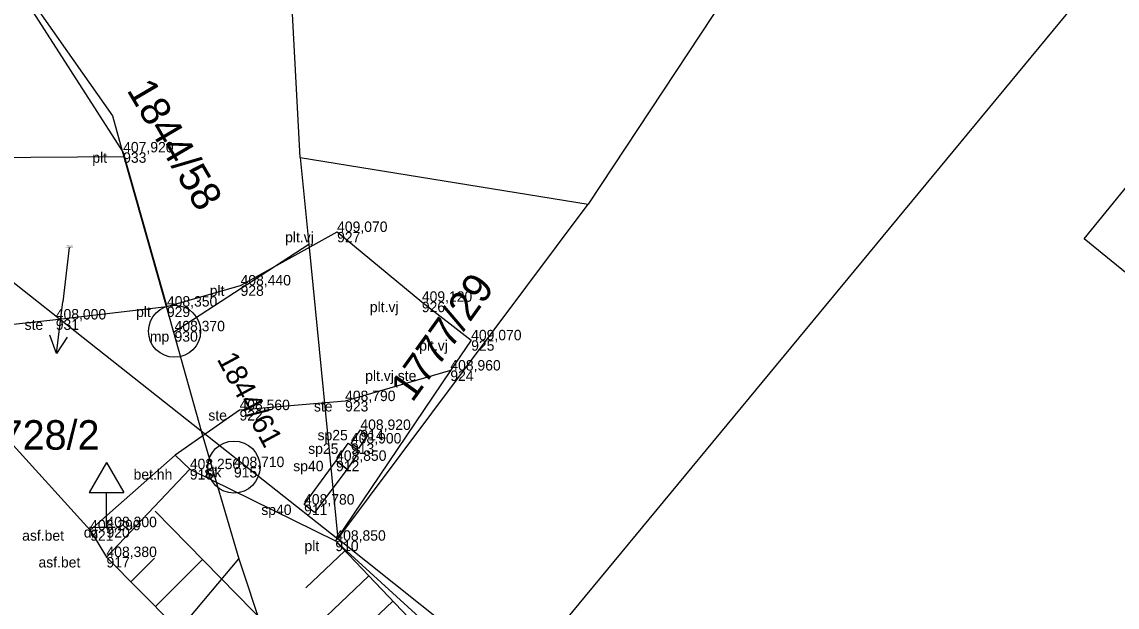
# Model space of a CAD drawing. Extents: x -747792 to -745414, y -1093712 to -1091463.
# Drawn here: x -746979.38 to -746947.84, y -1092227.92 to -1092211.07 of the extents above; entities that cross this region are included whole.
import ezdxf

# ---------------------------------------------------------------- set-up
doc = ezdxf.new("R2010")
doc.units = 0
for name, color, linetype in [('Doplňkové značky', 7, 'Continuous'), ('Hladina', 7, 'Continuous'), ('Koleje_dopravní prvky', 7, 'Continuous'), ('Nezařazené objekty', 7, 'Continuous'), ('Nivelační značky_hrany', 7, 'Continuous'), ('Názvy obcí_ulic', 7, 'Continuous'), ('Pracovní_bod PPBP', 7, 'Continuous'), ('Pracovní_bod PPBP - výška', 7, 'Continuous'), ('Rozhraní ploch', 7, 'Continuous'), ('Stromy_porost', 7, 'Continuous'), ('Výškopis', 7, 'Continuous'), ('Čísla popisná_parcelní', 7, 'Continuous')]:
    doc.layers.add(name, color=color, linetype=linetype)

msp = doc.modelspace()

# ---------------------------------------------------------------- linework, layer by layer
at = {"layer": 'Doplňkové značky'}
for points in [[(-746978.01, -1092217.57), (-746978.2, -1092219.13)], [(-746978.38, -1092220.619), (-746978.2, -1092219.13)], [(-746978.072, -1092220.153), (-746978.38, -1092220.619), (-746978.568, -1092220.093)]]:
    msp.add_lwpolyline(points, dxfattribs=at)
at = {"layer": 'Hladina'}
for p, q in [((-746976.46, -1092214.83), (-746976.46, -1092214.83)), ((-746970.3, -1092217.12), (-746970.3, -1092217.12)), ((-746973.08, -1092218.66), (-746973.08, -1092218.66)), ((-746967.86, -1092219.13), (-746967.86, -1092219.13)), ((-746975.2, -1092219.27), (-746975.2, -1092219.27)), ((-746978.4, -1092219.64), (-746978.4, -1092219.64)), ((-746974.98, -1092219.98), (-746974.98, -1092219.98)), ((-746966.44, -1092220.24), (-746966.44, -1092220.24)), ((-746967.04, -1092221.11), (-746967.04, -1092221.11)), ((-746970.07, -1092221.99), (-746970.07, -1092221.99)), ((-746973.11, -1092222.25), (-746973.11, -1092222.25)), ((-746969.63, -1092222.82), (-746969.63, -1092222.82)), ((-746969.9, -1092223.21), (-746969.9, -1092223.21)), ((-746973.27, -1092223.89), (-746973.27, -1092223.89)), ((-746970.33, -1092223.71), (-746970.33, -1092223.71)), ((-746974.54, -1092223.95), (-746974.54, -1092223.95)), ((-746971.25, -1092224.97), (-746971.25, -1092224.97)), ((-746977.41, -1092225.71), (-746977.41, -1092225.71)), ((-746976.94, -1092225.62), (-746976.94, -1092225.62)), ((-746970.35, -1092226.01), (-746970.35, -1092226.01)), ((-746976.94, -1092226.48), (-746976.94, -1092226.48))]:
    msp.add_line(p, q, dxfattribs=at)
at = {"layer": 'Nezařazené objekty'}
for points in [[(-746987.74, -1092189.24), (-746988.61, -1092192.03), (-746985.35, -1092204.92), (-746981.69, -1092206.7), (-746976.46, -1092214.83), (-746975.2, -1092219.27), (-746973.08, -1092218.66), (-746970.3, -1092217.12)], [(-746967.86, -1092219.13), (-746966.44, -1092220.24)], [(-746967.04, -1092221.11), (-746970.35, -1092226.01), (-746949.5, -1092245.03), (-746932.73, -1092224.69)]]:
    msp.add_lwpolyline(points, dxfattribs=at)
at = {"layer": 'Nivelační značky_hrany'}
for points in [[(-746898.18, -1092134.6), (-746904.12, -1092139.99), (-746912.01, -1092144.83), (-746920.08, -1092149.17), (-746928.02, -1092152.73), (-746936.45, -1092155.39), (-746944.61, -1092157.47), (-746953.75, -1092158.71), (-746964.92, -1092159.66), (-746970.4, -1092160.58), (-746974.78, -1092162.27), (-746978.42, -1092164.61), (-746982.83, -1092169.13), (-746985.04, -1092172.77), (-746987.83, -1092179.63), (-746991.85, -1092191.24), (-746993.29, -1092198.31), (-746992.77, -1092203.42), (-746990.96, -1092208.81), (-746987.41, -1092214.26), (-746982.51, -1092220.09), (-746977.41, -1092225.71), (-746976.94, -1092226.48)], [(-746982.51, -1092220.09), (-746978.4, -1092219.64), (-746975.2, -1092219.27)], [(-746967.04, -1092221.11), (-746970.07, -1092221.99), (-746973.11, -1092222.25), (-746974.96, -1092223.55)], [(-746976.94, -1092226.48), (-746974.54, -1092223.95), (-746974.96, -1092223.55), (-746977.41, -1092225.71)], [(-746976.94, -1092226.48), (-746970.22, -1092233.27), (-746962.6, -1092240.52), (-746956.57, -1092245.89), (-746954.31, -1092247.58)]]:
    msp.add_lwpolyline(points, dxfattribs=at)
at = {"layer": 'Názvy obcí_ulic'}
for p, q in [((-746976.94, -1092223.754), (-746977.44, -1092224.62)), ((-746976.94, -1092223.754), (-746976.44, -1092224.62)), ((-746977.44, -1092224.62), (-746976.44, -1092224.62)), ((-746976.94, -1092225.62), (-746976.94, -1092224.62)), ((-746977.19, -1092225.62), (-746976.69, -1092225.62))]:
    msp.add_line(p, q, dxfattribs=at)
msp.add_circle((-746974.98, -1092219.98), 0.75, dxfattribs=at)
at = {"layer": 'Pracovní_bod PPBP'}
msp.add_line((-746974.54, -1092223.95), (-746970.35, -1092226.01), dxfattribs=at)
for points in [[(-746952.71, -1092246.53), (-746961.45, -1092238.96), (-746966.16, -1092234.73), (-746975.539, -1092225.162)], [(-746951.23, -1092245.63), (-746959.67, -1092236.99), (-746961.76, -1092235.03), (-746970.35, -1092226.01)], [(-746970.075, -1092226.299), (-746971.199, -1092227.37)], [(-746976.237, -1092227.191), (-746975.555, -1092226.516)], [(-746975.533, -1092227.902), (-746974.173, -1092226.555)], [(-746969.385, -1092227.023), (-746971.624, -1092229.156)], [(-746968.695, -1092227.747), (-746969.81, -1092228.809)]]:
    msp.add_lwpolyline(points, dxfattribs=at)
at = {"layer": 'Pracovní_bod PPBP - výška'}
for points in [[(-746970.3, -1092217.12), (-746967.86, -1092219.13)], [(-746966.44, -1092220.24), (-746967.04, -1092221.11)]]:
    msp.add_lwpolyline(points, dxfattribs=at)
at = {"layer": 'Stromy_porost'}
for points in [[(-746950.17, -1092196.79), (-746963.07, -1092216.32)], [(-746971.36, -1092214.98), (-746971.93, -1092204.37)], [(-746965.16, -1092230.04), (-746943.99, -1092204.43)], [(-746981.78, -1092206.66), (-746976.77, -1092213.78)], [(-746948.79, -1092217.32), (-746944.69, -1092212.29)], [(-746976.77, -1092213.78), (-746976.44, -1092214.96)], [(-746976.44, -1092214.96), (-746983.14, -1092215.01)], [(-746976.44, -1092214.96), (-746975.01, -1092220.01)], [(-746971.36, -1092214.98), (-746963.07, -1092216.32)], [(-746971.36, -1092214.98), (-746971.11, -1092217.47)], [(-746970.28, -1092225.96), (-746963.07, -1092216.32)], [(-746975.01, -1092220.01), (-746971.11, -1092217.47)], [(-746971.11, -1092217.47), (-746970.28, -1092225.96)], [(-746946, -1092219.59), (-746948.79, -1092217.32)], [(-746980.19, -1092218.13), (-746974.21, -1092222.85)], [(-746975.01, -1092220.01), (-746974.21, -1092222.85)], [(-746974.21, -1092222.85), (-746973.13, -1092226.53)], [(-746974.21, -1092222.85), (-746970.28, -1092225.96)], [(-746965.49, -1092229.78), (-746970.28, -1092225.96)], [(-746980.14, -1092234.86), (-746973.13, -1092226.53)], [(-746973.13, -1092226.53), (-746964.93, -1092251.23)]]:
    msp.add_lwpolyline(points, dxfattribs=at)
at = {"layer": 'Čísla popisná_parcelní'}
for points in [[(-746969.9, -1092223.21), (-746969.63, -1092222.82), (-746969.422, -1092222.959), (-746969.681, -1092223.351), (-746969.9, -1092223.21)], [(-746970.33, -1092223.71), (-746969.98, -1092223.2), (-746969.652, -1092223.429), (-746970.01, -1092223.95), (-746970.33, -1092223.71)], [(-746971.25, -1092224.97), (-746970.33, -1092223.71), (-746970.01, -1092223.95), (-746970.948, -1092225.197), (-746971.25, -1092224.97)]]:
    msp.add_lwpolyline(points, dxfattribs=at)
msp.add_circle((-746973.27, -1092223.89), 0.75, dxfattribs=at)

# ---------------------------------------------------------------- texts
at = {"layer": 'Doplňkové značky'}
msp.add_text('1728/2', height=0.85, dxfattribs=at).set_placement((-746980.618, -1092223.39))
at = {"layer": 'Koleje_dopravní prvky'}
for s, height, rotation, p in [('1844/58', 0.85, 300.4018, (-746976.373, -1092213.035)), ('1777/29', 0.85, 54.3737, (-746968.136, -1092222.055)), ('1844/61', 0.61, 298.2245, (-746973.773, -1092220.78))]:
    msp.add_text(s, height=height, rotation=rotation, dxfattribs=at).set_placement(p)
msp.add_text('1728/2', height=0.05, dxfattribs=at).set_placement((-746978.125, -1092217.57))
at = {"layer": 'Rozhraní ploch'}
for s, p in [(' plt', (-746977.459, -1092215.13)), ('933', (-746976.46, -1092215.13)), (' plt.vj', (-746971.908, -1092217.42)), ('927', (-746970.3, -1092217.42)), (' plt', (-746974.079, -1092218.96)), ('928', (-746973.08, -1092218.96)), (' plt.vj', (-746969.468, -1092219.43)), ('926', (-746967.86, -1092219.43)), (' plt', (-746976.199, -1092219.57)), ('929', (-746975.2, -1092219.57)), (' ste', (-746979.409, -1092219.94)), ('931', (-746978.4, -1092219.94)), (' mp', (-746975.802, -1092220.28)), ('930', (-746974.98, -1092220.28)), (' plt.vj', (-746968.048, -1092220.54)), ('925', (-746966.44, -1092220.54)), (' plt.vj.ste', (-746969.602, -1092221.41)), ('924', (-746967.04, -1092221.41)), ('923', (-746970.07, -1092222.29)), (' ste', (-746974.119, -1092222.55)), ('922', (-746973.11, -1092222.55)), (' ste', (-746971.079, -1092222.29)), (' sp25', (-746970.974, -1092223.12)), ('914', (-746969.63, -1092223.12)), (' sp25', (-746971.244, -1092223.51)), ('913', (-746969.9, -1092223.51)), (' slk', (-746974.231, -1092224.19)), ('915', (-746973.27, -1092224.19)), (' sp40', (-746971.674, -1092224.01)), ('912', (-746970.33, -1092224.01)), (' bet.hh', (-746976.271, -1092224.25)), ('916', (-746974.54, -1092224.25)), (' sp40', (-746972.594, -1092225.27)), ('911', (-746971.25, -1092225.27)), (' asf.bet', (-746979.479, -1092226.01)), (' dz', (-746977.705, -1092225.92)), ('921', (-746977.41, -1092226.01)), ('920', (-746976.94, -1092225.92)), (' plt', (-746971.349, -1092226.31)), ('910', (-746970.35, -1092226.31)), (' asf.bet', (-746979.009, -1092226.78)), ('917', (-746976.94, -1092226.78))]:
    msp.add_text(s, height=0.3, dxfattribs=at).set_placement(p)
at = {"layer": 'Výškopis'}
for s, p in [('407,920', (-746976.46, -1092214.83)), ('409,070', (-746970.3, -1092217.12)), ('408,440', (-746973.08, -1092218.66)), ('409,120', (-746967.86, -1092219.13)), ('408,350', (-746975.2, -1092219.27)), ('408,000', (-746978.4, -1092219.64)), ('408,370', (-746974.98, -1092219.98)), ('409,070', (-746966.44, -1092220.24)), ('408,960', (-746967.04, -1092221.11)), ('408,790', (-746970.07, -1092221.99)), ('408,560', (-746973.11, -1092222.25)), ('408,920', (-746969.63, -1092222.82)), ('408,900', (-746969.9, -1092223.21)), ('408,850', (-746970.33, -1092223.71)), ('408,250', (-746974.54, -1092223.95)), ('408,710', (-746973.27, -1092223.89)), ('408,780', (-746971.25, -1092224.97)), ('408,290', (-746977.41, -1092225.71)), ('408,300', (-746976.94, -1092225.62)), ('408,850', (-746970.35, -1092226.01)), ('408,380', (-746976.94, -1092226.48))]:
    msp.add_text(s, height=0.3, dxfattribs=at).set_placement(p)

doc.saveas('drawing.dxf')
